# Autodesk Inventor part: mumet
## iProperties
Shininess: 64.0
Length Units: 11269
Angle Units: 11279
Time Units: 11290
Mass Units: 11283
Length Display Precision: 3
Angle Display Precision: 2
Compacted: True
Part Number: mumet
Document SubType Name: Modeling
Created: 2004-07
Designer: Peter
Manufacturer: Standard
Standards Organization: Custom
Density: 0.0
Volumn: 0.0
Area: 0.0
PropertySet Name: Model Information
Control State: 0
Master: False
Checked Out: False
Author: Peter
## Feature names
1. Revolution1
